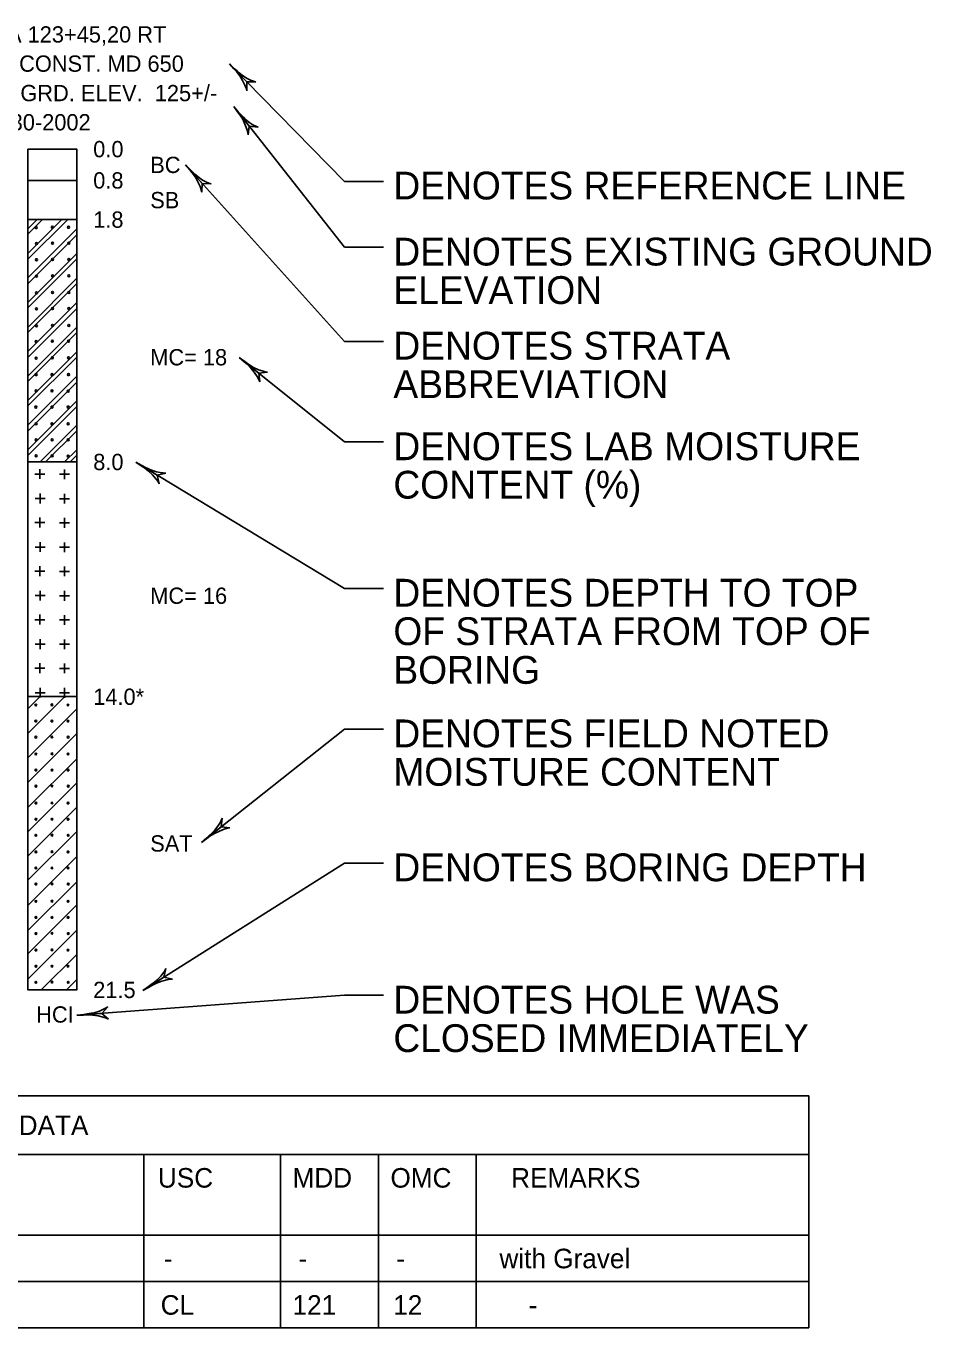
# Model space of a CAD drawing. Extents: x 1.3 to 42.5, y -2.5 to 22.6.
# Drawn here: x 23.44 to 27.34, y 5.49 to 11.11 of the extents above; entities that cross this region are included whole.
import ezdxf

# ---------------------------------------------------------------- set-up
doc = ezdxf.new("R2010")
doc.units = 0
doc.layers.add('B-SOIL-BORE', color=7, linetype='Continuous')

msp = doc.modelspace()

# ---------------------------------------------------------------- linework, layer by layer
at = {"layer": 'B-SOIL-BORE'}
for p, q in [((24.3133, 10.9467), (24.8097, 10.4403)), ((24.3135, 10.9469), (24.3135, 10.9469)), ((24.3891, 10.8697), (24.3135, 10.9469)), ((24.3323, 10.9257), (24.3135, 10.9469)), ((24.3351, 10.9265), (24.3135, 10.9469)), ((24.3437, 10.9141), (24.3323, 10.9257)), ((24.3465, 10.9169), (24.3351, 10.9265)), ((24.3577, 10.8957), (24.3437, 10.9141)), ((24.3597, 10.9053), (24.3465, 10.9169)), ((24.3701, 10.8967), (24.3597, 10.9053)), ((24.3699, 10.8755), (24.3577, 10.8957)), ((24.3801, 10.8555), (24.3699, 10.8755)), ((24.3901, 10.8839), (24.3701, 10.8967)), ((24.3859, 10.8421), (24.3801, 10.8555)), ((24.3891, 10.8697), (24.3885, 10.8315)), ((24.3891, 10.8697), (24.4271, 10.8693)), ((24.4045, 10.8771), (24.3901, 10.8839)), ((24.4167, 10.8723), (24.4045, 10.8771)), ((24.4271, 10.8693), (24.4167, 10.8723)), ((24.3885, 10.8315), (24.3859, 10.8421)), ((24.3319, 10.7635), (24.8098, 10.1561)), ((24.3321, 10.7637), (24.3321, 10.7637)), ((24.3989, 10.6787), (24.3321, 10.7637)), ((24.3485, 10.7405), (24.3321, 10.7637)), ((24.3515, 10.7411), (24.3321, 10.7637)), ((24.3585, 10.7279), (24.3485, 10.7405)), ((24.3615, 10.7303), (24.3515, 10.7411)), ((24.3737, 10.7173), (24.3615, 10.7303)), ((24.3705, 10.7081), (24.3585, 10.7279)), ((24.3805, 10.6869), (24.3705, 10.7081)), ((24.3829, 10.7077), (24.3737, 10.7173)), ((24.3885, 10.6655), (24.3805, 10.6869)), ((24.4015, 10.6931), (24.3829, 10.7077)), ((24.3989, 10.6787), (24.3943, 10.6409)), ((24.3989, 10.6787), (24.4367, 10.6743)), ((24.4147, 10.6847), (24.4015, 10.6931)), ((24.4267, 10.6785), (24.4147, 10.6847)), ((24.4367, 10.6743), (24.4267, 10.6785)), ((24.3927, 10.6517), (24.3885, 10.6655)), ((24.3943, 10.6409), (24.3927, 10.6517)), ((24.1239, 10.5119), (24.1239, 10.5119)), ((24.1963, 10.4317), (24.1239, 10.5119)), ((24.1421, 10.4899), (24.1239, 10.5119)), ((24.1451, 10.4907), (24.1239, 10.5119)), ((24.1239, 10.5118), (24.8098, 9.75)), ((24.1529, 10.4779), (24.1421, 10.4899)), ((24.1559, 10.4805), (24.1451, 10.4907)), ((24.1663, 10.4589), (24.1529, 10.4779)), ((24.1685, 10.4683), (24.1559, 10.4805)), ((24.1777, 10.4385), (24.1663, 10.4589)), ((24.1787, 10.4595), (24.1685, 10.4683)), ((24.1979, 10.4459), (24.1787, 10.4595)), ((24.1871, 10.4179), (24.1777, 10.4385)), ((24.1919, 10.4041), (24.1871, 10.4179)), ((24.1945, 10.3935), (24.1919, 10.4041)), ((24.1963, 10.4317), (24.1945, 10.3935)), ((24.1963, 10.4317), (24.2343, 10.4297)), ((24.2119, 10.4385), (24.1979, 10.4459)), ((24.2241, 10.4331), (24.2119, 10.4385)), ((24.2343, 10.4297), (24.2241, 10.4331)), ((24.9785, 10.4403), (24.8098, 10.4403)), ((23.5075, 10.276), (23.4439, 10.2124)), ((23.4842, 10.276), (23.4439, 10.2357)), ((23.591, 10.276), (23.4439, 10.1288)), ((23.6157, 10.276), (23.4439, 10.1042)), ((23.6549, 10.2357), (23.4439, 10.0247)), ((23.6549, 10.2097), (23.4439, 9.9987)), ((23.6549, 10.1289), (23.4439, 9.9179)), ((24.9785, 10.1561), (24.8098, 10.1561)), ((23.6549, 10.1056), (23.4439, 9.8946)), ((23.6549, 10.022), (23.4446, 9.8117)), ((23.6549, 10.0001), (23.446, 9.7911)), ((23.6549, 9.9179), (23.4439, 9.7069)), ((23.6549, 9.8919), (23.4439, 9.6808)), ((23.6549, 9.811), (23.4439, 9.6)), ((23.6549, 9.7877), (23.4439, 9.5767)), ((24.9785, 9.75), (24.8098, 9.75)), ((23.6549, 9.7055), (23.4439, 9.4945)), ((23.6549, 9.6822), (23.4439, 9.4712)), ((24.3553, 9.6803), (24.3553, 9.6803)), ((24.4399, 9.6127), (24.3553, 9.6803)), ((24.3767, 9.6617), (24.3553, 9.6803)), ((24.3793, 9.6627), (24.3553, 9.6803)), ((24.3553, 9.6802), (24.8098, 9.3161)), ((24.3893, 9.6513), (24.3767, 9.6617)), ((24.3917, 9.6547), (24.3793, 9.6627)), ((24.4055, 9.6349), (24.3893, 9.6513)), ((24.4063, 9.6447), (24.3917, 9.6547)), ((24.4201, 9.6165), (24.4055, 9.6349)), ((24.4177, 9.6373), (24.4063, 9.6447)), ((24.4391, 9.6271), (24.4177, 9.6373)), ((24.4329, 9.5977), (24.4201, 9.6165)), ((24.4541, 9.6223), (24.4391, 9.6271)), ((24.4399, 9.6127), (24.4777, 9.6171)), ((24.4399, 9.6127), (24.4439, 9.5749)), ((24.4669, 9.6187), (24.4541, 9.6223)), ((24.4777, 9.6171), (24.4669, 9.6187)), ((23.6549, 9.6), (23.4439, 9.389)), ((23.6549, 9.574), (23.4439, 9.363)), ((24.4399, 9.5849), (24.4329, 9.5977)), ((24.4439, 9.5749), (24.4399, 9.5849)), ((23.6549, 9.4932), (23.4439, 9.2822)), ((23.6549, 9.4685), (23.4439, 9.2575)), ((23.6549, 9.3877), (23.497, 9.2297)), ((23.6549, 9.3644), (23.5203, 9.2297)), ((23.6549, 9.2822), (23.6025, 9.2297)), ((24.9785, 9.3161), (24.8098, 9.3161)), ((23.6549, 9.2589), (23.6257, 9.2297)), ((23.909, 9.2284), (24.8098, 8.684)), ((23.9091, 9.2285), (23.9091, 9.2285)), ((24.0017, 9.1727), (23.9091, 9.2285)), ((23.9327, 9.2129), (23.9091, 9.2285)), ((23.9353, 9.2145), (23.9091, 9.2285)), ((23.9487, 9.2077), (23.9353, 9.2145)), ((23.4739, 9.1772), (23.5167, 9.1772)), ((23.4953, 9.1983), (23.4953, 9.1561)), ((23.496, 9.1991), (23.496, 9.1569)), ((23.5808, 9.1765), (23.6237, 9.1765)), ((23.6022, 9.1976), (23.6022, 9.1554)), ((23.9465, 9.2045), (23.9327, 9.2129)), ((23.9649, 9.1903), (23.9465, 9.2045)), ((23.9643, 9.1999), (23.9487, 9.2077)), ((23.9765, 9.1939), (23.9643, 9.1999)), ((23.9817, 9.1737), (23.9649, 9.1903)), ((23.9989, 9.1869), (23.9765, 9.1939)), ((23.9965, 9.1567), (23.9817, 9.1737)), ((24.0147, 9.1837), (23.9989, 9.1869)), ((24.0017, 9.1727), (24.0387, 9.1819)), ((24.0017, 9.1727), (24.0109, 9.1357)), ((24.0279, 9.1821), (24.0147, 9.1837)), ((24.0387, 9.1819), (24.0279, 9.1821)), ((24.0055, 9.1451), (23.9965, 9.1567)), ((24.0109, 9.1357), (24.0055, 9.1451)), ((23.4754, 9.0717), (23.5182, 9.0717)), ((23.4968, 9.0928), (23.4968, 9.0506)), ((23.5808, 9.071), (23.6237, 9.071)), ((23.6022, 9.0921), (23.6022, 9.0499)), ((23.4953, 8.9889), (23.4953, 8.9467)), ((23.496, 8.9896), (23.496, 8.9474)), ((23.4739, 8.9678), (23.5167, 8.9678)), ((23.5808, 8.967), (23.6237, 8.967)), ((23.6022, 8.9881), (23.6022, 8.9459)), ((23.4968, 8.8834), (23.4968, 8.8412)), ((23.6022, 8.8827), (23.6022, 8.8405)), ((23.4754, 8.8623), (23.5182, 8.8623)), ((23.5808, 8.8616), (23.6237, 8.8616)), ((23.4953, 8.7794), (23.4953, 8.7372)), ((23.496, 8.7802), (23.496, 8.738)), ((23.6022, 8.7787), (23.6022, 8.7365)), ((23.4739, 8.7583), (23.5167, 8.7583)), ((23.5808, 8.7576), (23.6237, 8.7576)), ((23.4754, 8.6529), (23.5182, 8.6529)), ((23.4968, 8.674), (23.4968, 8.6318)), ((23.5808, 8.6521), (23.6237, 8.6521)), ((23.6022, 8.6732), (23.6022, 8.631)), ((24.9785, 8.684), (24.8098, 8.684)), ((23.4739, 8.5489), (23.5167, 8.5489)), ((23.4953, 8.57), (23.4953, 8.5278)), ((23.496, 8.5707), (23.496, 8.5285)), ((23.5808, 8.5481), (23.6237, 8.5481)), ((23.6022, 8.5692), (23.6022, 8.527)), ((23.4754, 8.4434), (23.5182, 8.4434)), ((23.4968, 8.4645), (23.4968, 8.4223)), ((23.5808, 8.4427), (23.6237, 8.4427)), ((23.6022, 8.4638), (23.6022, 8.4216)), ((23.4739, 8.3395), (23.5167, 8.3395)), ((23.4953, 8.3606), (23.4953, 8.3184)), ((23.496, 8.3613), (23.496, 8.3191)), ((23.5808, 8.3387), (23.6237, 8.3387)), ((23.6022, 8.3598), (23.6022, 8.3176)), ((23.4439, 8.0585), (23.6026, 8.2172)), ((23.4439, 8.165), (23.4962, 8.2172)), ((23.4754, 8.234), (23.5182, 8.234)), ((23.4968, 8.2551), (23.4968, 8.2129)), ((23.5808, 8.2332), (23.6237, 8.2332)), ((23.6022, 8.2543), (23.6022, 8.2121)), ((23.4439, 7.953), (23.6549, 8.164)), ((23.4439, 7.8465), (23.6549, 8.0575)), ((24.193, 7.588), (24.8098, 8.0767)), ((24.9785, 8.0767), (24.8098, 8.0767)), ((23.4439, 7.7379), (23.6549, 7.9489)), ((23.4439, 7.6334), (23.6549, 7.8444)), ((23.4439, 7.5289), (23.6549, 7.7399)), ((24.2779, 7.6553), (24.1931, 7.5881)), ((24.2635, 7.6577), (24.2489, 7.6393)), ((24.2719, 7.6711), (24.2635, 7.6577)), ((24.2911, 7.6449), (24.2701, 7.6369)), ((24.2781, 7.6831), (24.2719, 7.6711)), ((24.2779, 7.6553), (24.2821, 7.6931)), ((24.2779, 7.6553), (24.3157, 7.6507)), ((24.2821, 7.6931), (24.2781, 7.6831)), ((24.3049, 7.6491), (24.2911, 7.6449)), ((24.3157, 7.6507), (24.3049, 7.6491)), ((23.4439, 7.4244), (23.6549, 7.6354)), ((24.2155, 7.6077), (24.1931, 7.5881)), ((24.2163, 7.6047), (24.1931, 7.5881)), ((24.1931, 7.5881), (24.1931, 7.5881)), ((24.2263, 7.6179), (24.2155, 7.6077)), ((24.2289, 7.6147), (24.2163, 7.6047)), ((24.2393, 7.6299), (24.2263, 7.6179)), ((24.2487, 7.6269), (24.2289, 7.6147)), ((24.2489, 7.6393), (24.2393, 7.6299)), ((24.2701, 7.6369), (24.2487, 7.6269)), ((23.4439, 7.3159), (23.6549, 7.5269)), ((23.9394, 6.9484), (24.8098, 7.4983)), ((24.9785, 7.4983), (24.8098, 7.4983)), ((23.4439, 7.2073), (23.6549, 7.4183)), ((23.4439, 7.1068), (23.6549, 7.3179)), ((23.4439, 6.9983), (23.6549, 7.2093)), ((23.5017, 6.9516), (23.6549, 7.1048)), ((24.0267, 7.0229), (24.0171, 7.0103)), ((24.0341, 7.0339), (24.0267, 7.0229)), ((24.0309, 7.0061), (24.0391, 7.0435)), ((24.0391, 7.0435), (24.0341, 7.0339)), ((23.6102, 6.9516), (23.6549, 6.9963)), ((24.0309, 7.0061), (23.9395, 6.9487)), ((23.9757, 6.9745), (23.9639, 6.9657)), ((23.9779, 6.9711), (23.9641, 6.9625)), ((23.9897, 6.9851), (23.9757, 6.9745)), ((23.9987, 6.9811), (23.9779, 6.9711)), ((24.0005, 6.9935), (23.9897, 6.9851)), ((24.0211, 6.9889), (23.9987, 6.9811)), ((24.0171, 7.0103), (24.0005, 6.9935)), ((24.0429, 6.9945), (24.0211, 6.9889)), ((24.0309, 7.0061), (24.0681, 6.9979)), ((24.0573, 6.9973), (24.0429, 6.9945)), ((24.0681, 6.9979), (24.0573, 6.9973)), ((23.6554, 6.8418), (24.8098, 6.9281)), ((23.9639, 6.9657), (23.9395, 6.9487)), ((23.9641, 6.9625), (23.9395, 6.9487)), ((23.9395, 6.9487), (23.9395, 6.9487)), ((24.9785, 6.9281), (24.8098, 6.9281)), ((23.7529, 6.8601), (23.7305, 6.8531)), ((23.7673, 6.8665), (23.7529, 6.8601)), ((23.7633, 6.8501), (23.7881, 6.8791)), ((23.7791, 6.8727), (23.7673, 6.8665)), ((23.7881, 6.8791), (23.7791, 6.8727)), ((23.7633, 6.8501), (23.6555, 6.8421)), ((23.6849, 6.8455), (23.6555, 6.8421)), ((23.6839, 6.8429), (23.6555, 6.8421)), ((23.6555, 6.8421), (23.6555, 6.8421)), ((23.7001, 6.8439), (23.6839, 6.8429)), ((23.6997, 6.8479), (23.6849, 6.8455)), ((23.7171, 6.8507), (23.6997, 6.8479)), ((23.7231, 6.8429), (23.7001, 6.8439)), ((23.7305, 6.8531), (23.7171, 6.8507)), ((23.7465, 6.8393), (23.7231, 6.8429)), ((23.7683, 6.8341), (23.7465, 6.8393)), ((23.7633, 6.8501), (23.7921, 6.8251)), ((23.7825, 6.8299), (23.7683, 6.8341)), ((23.7921, 6.8251), (23.7825, 6.8299)), ((19.8937, 6.4947), (26.8125, 6.4947)), ((26.8125, 6.4947), (26.8125, 6.2416)), ((19.8937, 6.2416), (26.8125, 6.2416)), ((23.9437, 6.2416), (23.9437, 6.0412)), ((24.5343, 6.2416), (24.5343, 6.0412)), ((24.9562, 6.2416), (24.9562, 6.0412)), ((25.3781, 6.2416), (25.3781, 6.0412)), ((26.8125, 6.2416), (26.8125, 6.0412)), ((23.9437, 6.0939), (23.9437, 5.8935)), ((24.5343, 6.0939), (24.5343, 5.8935)), ((24.9562, 6.0939), (24.9562, 5.8935)), ((25.3781, 6.0939), (25.3781, 5.8935)), ((26.8125, 6.0939), (26.8125, 5.8935)), ((19.8937, 5.8935), (26.8125, 5.8935)), ((23.9437, 5.8935), (23.9437, 5.6931)), ((24.5343, 5.8935), (24.5343, 5.6931)), ((24.9562, 5.8935), (24.9562, 5.6931)), ((25.3781, 5.8935), (25.3781, 5.6931)), ((26.8125, 5.8935), (26.8125, 5.6931)), ((19.8937, 5.6931), (26.8125, 5.6931)), ((23.9437, 5.6931), (23.9437, 5.4927)), ((24.5343, 5.6931), (24.5343, 5.4927)), ((24.9562, 5.6931), (24.9562, 5.4927)), ((25.3781, 5.6931), (25.3781, 5.4927)), ((26.8125, 5.6931), (26.8125, 5.4927)), ((19.8937, 5.4927), (26.8125, 5.4927))]:
    msp.add_line(p, q, dxfattribs=at)
for points in [[(23.4439, 10.5797), (23.4439, 10.4447), (23.6549, 10.4447), (23.6549, 10.5797)], [(23.4439, 10.4447), (23.4439, 10.276), (23.6549, 10.276), (23.6549, 10.4447)], [(23.4439, 10.276), (23.6549, 10.276), (23.6549, 9.2297), (23.4439, 9.2297)], [(23.4439, 9.2297), (23.6549, 9.2297), (23.6549, 8.2172), (23.4439, 8.2172)], [(23.4439, 8.2172), (23.6549, 8.2172), (23.6549, 6.9516), (23.4439, 6.9516)]]:
    msp.add_lwpolyline(points, close=True, dxfattribs=at)
for centre, radius in [((23.4794, 10.2407), 0.00429), ((23.5493, 10.2421), 0.00429), ((23.6191, 10.2421), 0.00429), ((23.4808, 10.1722), 0.00429), ((23.5506, 10.1736), 0.00429), ((23.6205, 10.1736), 0.00429), ((23.4808, 10.1024), 0.00429), ((23.5506, 10.1037), 0.00429), ((23.6205, 10.1037), 0.00429), ((23.4808, 10.0311), 0.00429), ((23.5506, 10.0325), 0.00429), ((23.6205, 10.0325), 0.00429), ((23.4808, 9.9599), 0.00429), ((23.5506, 9.9612), 0.00429), ((23.6205, 9.9612), 0.00429), ((23.4808, 9.89), 0.00429), ((23.5506, 9.8914), 0.00429), ((23.6205, 9.8914), 0.00429), ((23.4808, 9.8174), 0.00429), ((23.5506, 9.8188), 0.00429), ((23.6205, 9.8188), 0.00429), ((23.4794, 9.7489), 0.00429), ((23.5493, 9.7503), 0.00429), ((23.6191, 9.7503), 0.00429), ((23.4794, 9.6776), 0.00429), ((23.5493, 9.679), 0.00429), ((23.6191, 9.679), 0.00429), ((23.4794, 9.6064), 0.00429), ((23.5479, 9.6064), 0.00429), ((23.6191, 9.6064), 0.00429), ((23.4794, 9.5365), 0.00429), ((23.5479, 9.5365), 0.00429), ((23.6177, 9.5351), 0.00429), ((23.478, 9.4666), 0.00429), ((23.5479, 9.4666), 0.00429), ((23.6177, 9.4666), 0.00429), ((23.4794, 9.394), 0.00429), ((23.5479, 9.394), 0.00429), ((23.6177, 9.394), 0.00429), ((23.4794, 9.3255), 0.00429), ((23.5481, 9.3247), 0.00429), ((23.6176, 9.3247), 0.00429), ((23.4794, 9.2556), 0.00429), ((23.5485, 9.2555), 0.00429), ((23.6176, 9.2551), 0.00429), ((23.4782, 8.1808), 0.00373), ((23.5476, 8.1816), 0.00373), ((23.617, 8.1808), 0.00373), ((23.4782, 8.1114), 0.00373), ((23.5476, 8.1114), 0.00373), ((23.617, 8.1114), 0.00373), ((23.4782, 8.042), 0.00373), ((23.5476, 8.0428), 0.00373), ((23.6177, 8.042), 0.00373), ((23.4784, 7.9693), 0.00373), ((23.5478, 7.97), 0.00373), ((23.6172, 7.9693), 0.00373), ((23.4784, 7.8999), 0.00373), ((23.5478, 7.8999), 0.00373), ((23.6172, 7.8999), 0.00373), ((23.4784, 7.8305), 0.00373), ((23.5478, 7.8312), 0.00373), ((23.6179, 7.8305), 0.00373), ((23.4784, 7.7574), 0.00373), ((23.5478, 7.7581), 0.00373), ((23.6172, 7.7574), 0.00373), ((23.4784, 7.688), 0.00373), ((23.5478, 7.688), 0.00373), ((23.6172, 7.688), 0.00373), ((23.4784, 7.6186), 0.00373), ((23.5478, 7.6193), 0.00373), ((23.6179, 7.6186), 0.00373), ((23.4784, 7.5469), 0.00373), ((23.5478, 7.5477), 0.00373), ((23.6172, 7.5469), 0.00373), ((23.4784, 7.4775), 0.00373), ((23.5478, 7.4775), 0.00373), ((23.6172, 7.4775), 0.00373), ((23.4784, 7.4082), 0.00373), ((23.5478, 7.4089), 0.00373), ((23.6179, 7.4082), 0.00373), ((23.4784, 7.3335), 0.00373), ((23.5478, 7.3343), 0.00373), ((23.6172, 7.3335), 0.00373), ((23.4784, 7.2641), 0.00373), ((23.5478, 7.2641), 0.00373), ((23.6172, 7.2641), 0.00373), ((23.4784, 7.1947), 0.00373), ((23.5478, 7.1955), 0.00373), ((23.6179, 7.1947), 0.00373), ((23.4784, 7.1231), 0.00373), ((23.5478, 7.1239), 0.00373), ((23.6171, 7.1231), 0.00373), ((23.4784, 7.0537), 0.00373), ((23.5478, 7.0537), 0.00373), ((23.6171, 7.0537), 0.00373), ((23.4784, 6.9843), 0.00373), ((23.5478, 6.9851), 0.00373), ((23.6179, 6.9843), 0.00373)]:
    msp.add_circle(centre, radius, dxfattribs=at)

# ---------------------------------------------------------------- texts
for s, height, p in [('STA 123+45,20 RT', 0.070308, (23.2337, 11.0393)), ('C/L CONST. MD 650', 0.070308, (23.2337, 10.9133)), ('EX. GRD. ELEV.  125+/-', 0.070308, (23.2337, 10.7863)), ('09-30-2002', 0.07031, (23.2337, 10.6603)), ('0.0', 0.07031, (23.7257, 10.5443)), ('BC', 0.07031, (23.9717, 10.4763)), ('0.8', 0.07031, (23.7257, 10.4093)), ('DENOTES REFERENCE LINE', 0.12, (25.0207, 10.3623)), ('SB', 0.07031, (23.9717, 10.3243)), ('1.8', 0.07031, (23.7257, 10.2403)), ('DENOTES EXISTING GROUND', 0.12, (25.0207, 10.0773)), ('ELEVATION', 0.12, (25.0207, 9.9113)), ('DENOTES STRATA', 0.12, (25.0207, 9.6713)), ('MC= 18', 0.07031, (23.9717, 9.6463)), ('ABBREVIATION', 0.12, (25.0207, 9.5053)), ('DENOTES LAB MOISTURE', 0.12, (25.0207, 9.2373)), ('8.0', 0.07031, (23.7257, 9.1943)), ('CONTENT (%)', 0.12, (25.0207, 9.0713)), ('DENOTES DEPTH TO TOP', 0.12, (25.0207, 8.6053)), ('MC= 16', 0.07031, (23.9717, 8.6173)), ('OF STRATA FROM TOP OF', 0.12, (25.0207, 8.4393)), ('BORING', 0.12, (25.0207, 8.2723)), ('14.0*', 0.07031, (23.7257, 8.1813)), ('DENOTES FIELD NOTED', 0.12, (25.0207, 7.9983)), ('MOISTURE CONTENT', 0.12, (25.0207, 7.8323)), ('SAT', 0.07031, (23.9717, 7.5483)), ('DENOTES BORING DEPTH', 0.12, (25.0207, 7.4203)), ('21.5', 0.07031, (23.7257, 6.9163)), ('DENOTES HOLE WAS', 0.12, (25.0207, 6.8493)), ('HCI', 0.07031, (23.4797, 6.8103)), ('CLOSED IMMEDIATELY', 0.12, (25.0207, 6.6833)), ('SOILS TEST DATA', 0.08437, (22.7208, 6.3251)), ('USC', 0.08437, (24.0048, 6.0983)), (' MDD', 0.08437, (24.5544, 6.0983)), (' OMC', 0.08437, (24.9768, 6.0983)), ('REMARKS', 0.08437, (25.5288, 6.0983)), ('-', 0.0844, (24.03, 5.7503)), (' -', 0.08437, (24.5796, 5.7503)), (' -', 0.08437, (25.002, 5.7503)), ('with Gravel', 0.08437, (25.4784, 5.7503)), ('CL', 0.08437, (24.0168, 5.5499)), (' 121', 0.08437, (24.5544, 5.5499)), (' 12', 0.08437, (24.9888, 5.5499)), ('-', 0.0844, (25.6044, 5.5499))]:
    msp.add_text(s, height=height, dxfattribs=at).set_placement(p)

doc.saveas('drawing.dxf')
